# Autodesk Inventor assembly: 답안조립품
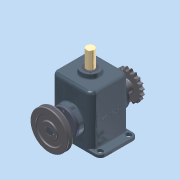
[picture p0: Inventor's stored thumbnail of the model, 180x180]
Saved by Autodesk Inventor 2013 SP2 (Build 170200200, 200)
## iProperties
Created: 2015-03
Part Number: 답안조립품
Document SubType Name: Assembly
Designer: dgall
Mass: 8579.11 g
Surface Area: 4386.54 cm^2
Volume: 1982.52 cm^3
Density: 4.32738 g/cm^3
Author: dgall
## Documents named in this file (15)
- C:\Documents and Settings\dgall\바탕 화면\350305V1031\답안조립품.iam
- C:\Documents and Settings\dgall\바탕 화면\350305V1031\본체.ipt
- C:\Documents and Settings\dgall\바탕 화면\350305V1031\V-벨트풀리.ipt
- C:\Documents and Settings\dgall\바탕 화면\350305V1031\오일실.ipt
- C:\Documents and Settings\dgall\바탕 화면\350305V1031\M4x0.5.ipt
- C:\Documents and Settings\dgall\바탕 화면\350305V1031\베어링 6205.ipt
- C:\Documents and Settings\dgall\바탕 화면\350305V1031\멈춤링.ipt
- C:\Documents and Settings\dgall\바탕 화면\350305V1031\키 8x8.ipt
- C:\Documents and Settings\dgall\바탕 화면\350305V1031\편심축.ipt
- C:\Documents and Settings\dgall\바탕 화면\350305V1031\가변스프링.ipt
- C:\Documents and Settings\dgall\바탕 화면\350305V1031\슬라이드.ipt
- C:\Documents and Settings\dgall\바탕 화면\350305V1031\커버.ipt
- C:\Documents and Settings\dgall\바탕 화면\350305V1031\체인 스프로킷.ipt
- C:\Documents and Settings\dgall\바탕 화면\350305V1031\멈춤나사 M5x0.5.ipt
- C:\Documents and Settings\dgall\바탕 화면\350305V1031\부시.ipt
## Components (9 placed, 4 different names)
1. V-벨트풀리:1
2. M4x0.5:1
3. M4x0.5:2
4. M4x0.5:3
5. 가변스프링:1
6. M4x0.5:5
7. M4x0.5:6
8. M4x0.5:7
9. 5-체인 스프로킷:1
